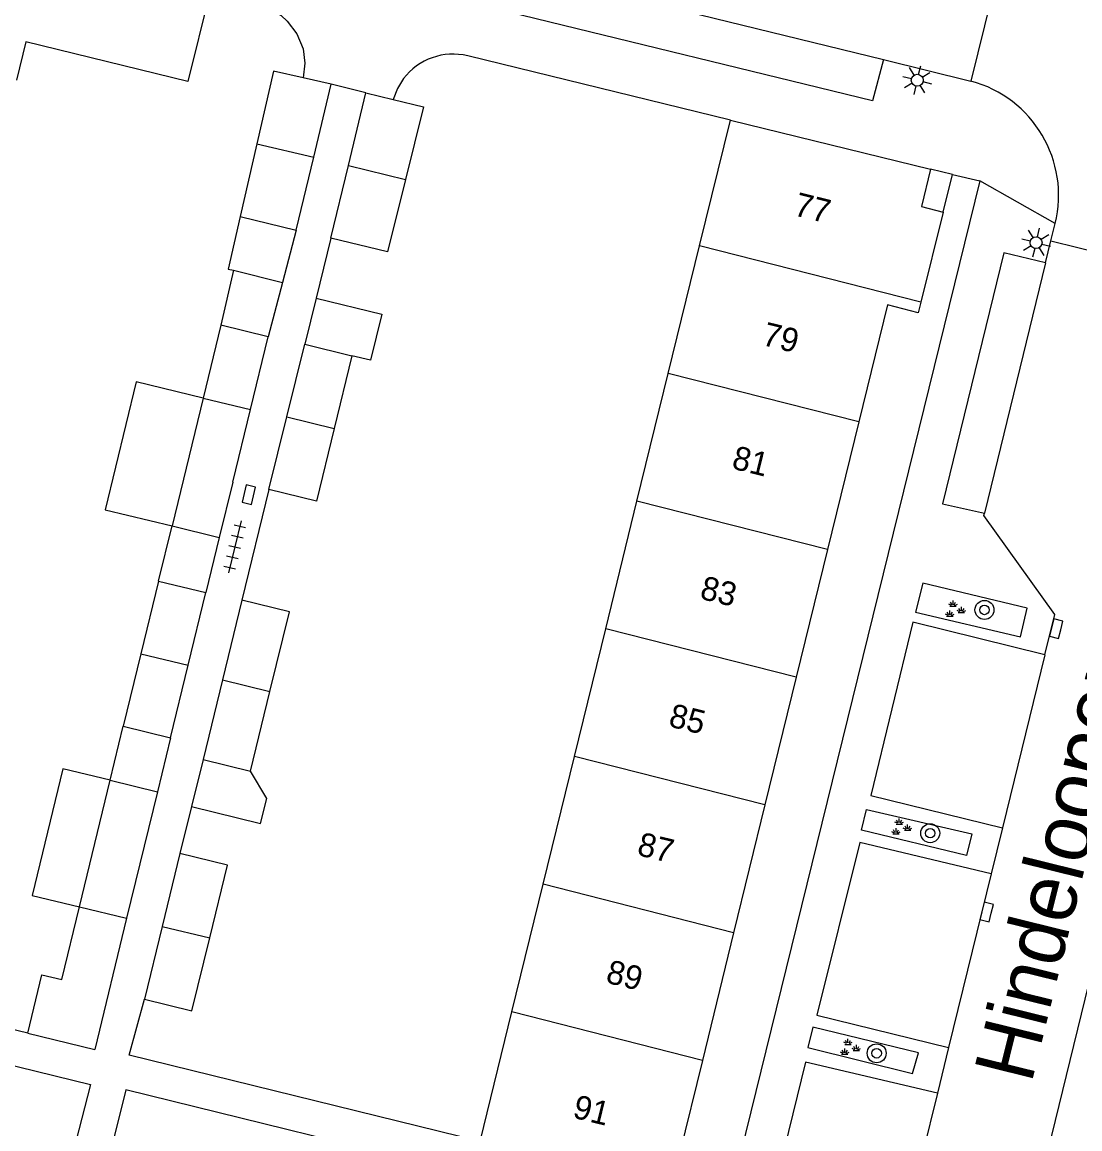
# Model space of a CAD drawing. Extents: x 128000 to 131008, y 398996 to 402500.
# Drawn here: x 128064.32 to 128108.9, y 399441.34 to 399488.01 of the extents above; entities that cross this region are included whole.
import ezdxf

# ---------------------------------------------------------------- set-up
doc = ezdxf.new("R2010")
doc.units = 0
for name, color, linetype in [('gg-afsc-erfafscheiding', 7, 'Continuous'), ('gg-afsc-muur', 7, 'Continuous'), ('gg-anno-huisnummerreeks BGT', 7, 'Continuous'), ('gg-anno-openbare ruimte label', 7, 'Continuous'), ('gg-bbg-bijgebouw', 7, 'Continuous'), ('gg-bbg-gedigitaliseerde bebouwing', 7, 'Continuous'), ('gg-bbg-gedigitaliseerde bijgebouw', 7, 'Continuous'), ('gg-bbg-hoofdgebouw', 7, 'Continuous'), ('gg-bbg-luifel en loopbrug', 7, 'Continuous'), ('gg-bbg-onder overbouw', 7, 'Continuous'), ('gg-bbg-pand overbouw', 7, 'Continuous'), ('gg-bbg-tussenscheiding', 7, 'Continuous'), ('gg-knt-verharding', 7, 'Continuous'), ('gg-knt-verharding nz', 7, 'Continuous'), ('gt-grn-weggrens', 7, 'Continuous'), ('gt-symb-boom', 7, 'Continuous'), ('gt-symb-groenvak', 7, 'Continuous'), ('gt-symb-kolk', 7, 'Continuous'), ('gt-symb-lichtmast', 7, 'Continuous'), ('gt-symb-tegel verharding', 7, 'Continuous')]:
    doc.layers.add(name, color=color, linetype=linetype)

# ---------------------------------------------------------------- blocks, each defined once
blk = doc.blocks.new('gt0-BOOM')
at = {"layer": 'gt-symb-boom'}
for radius in [0.4, 0.2]:
    blk.add_circle((0, 0), radius, dxfattribs=at)
blk = doc.blocks.new('gt0-LMAST')
at = {"layer": 'gt-symb-lichtmast'}
for p, q in [((-0.005, 0.246), (-0.005, 0.621)), ((-0.182, 0.173), (-0.447, 0.438)), ((0.172, 0.173), (0.437, 0.438)), ((-0.255, -0.004), (-0.63, -0.004)), ((-0.182, -0.181), (-0.447, -0.446)), ((-0.005, -0.254), (-0.005, -0.629)), ((0.437, -0.446), (0.172, -0.181)), ((0.245, -0.004), (0.62, -0.004))]:
    blk.add_line(p, q, dxfattribs=at)
blk.add_circle((-0.005, -0.004), 0.25, dxfattribs=at)
blk = doc.blocks.new('gt0-KOLK')
at = {"layer": 'gt-symb-kolk'}
blk.add_lwpolyline([(0, 0), (0.375, 0), (0.375, 0.4), (-0.375, 0.4), (-0.375, 0), (0, 0)], dxfattribs=at)
blk = doc.blocks.new('gt0-GRVAK')
at = {"layer": 'gt-symb-groenvak'}
for p, q in [((-0.11, 0.189), (-0.228, 0.24)), ((-0.182, 0.153), (0.088, 0.153)), ((-0.091, 0.211), (-0.156, 0.322)), ((-0.047, 0.214), (-0.047, 0.393)), ((-0.004, 0.211), (0.061, 0.322)), ((0.015, 0.189), (0.133, 0.24)), ((0.262, -0.052), (0.197, 0.059)), ((0.305, -0.049), (0.305, 0.13)), ((0.349, -0.052), (0.414, 0.059)), ((-0.245, -0.228), (-0.363, -0.177)), ((-0.318, -0.264), (-0.047, -0.264)), ((-0.226, -0.206), (-0.291, -0.095)), ((-0.183, -0.203), (-0.183, -0.024)), ((-0.139, -0.206), (-0.074, -0.095)), ((-0.12, -0.228), (-0.002, -0.177)), ((0.243, -0.074), (0.125, -0.023)), ((0.17, -0.11), (0.441, -0.11)), ((0.368, -0.074), (0.486, -0.023))]:
    blk.add_line(p, q, dxfattribs=at)
blk = doc.blocks.new('gt0-TEG1')
at = {"layer": 'gt-symb-tegel verharding'}
for p, q in [((-1.125, 0), (1.125, 0)), ((-0.9, -0.25), (-0.9, 0.25)), ((-0.45, -0.25), (-0.45, 0.25)), ((0, -0.25), (0, 0.25)), ((0.45, -0.25), (0.45, 0.25)), ((0.9, -0.25), (0.9, 0.25))]:
    blk.add_line(p, q, dxfattribs=at)

msp = doc.modelspace()

# ---------------------------------------------------------------- linework, layer by layer
at = {"layer": 'gg-afsc-erfafscheiding'}
for p, q in [((128077.332, 399478.897), (128076.707, 399476.366)), ((128074.717, 399468.301), (128073.578, 399463.633)), ((128071.46, 399454.927), (128070.97, 399452.944)), ((128064.553, 399445.371), (128054.591, 399447.82))]:
    msp.add_line(p, q, dxfattribs=at)
for points in [[(128083.621, 399440.81), (128068.828, 399444.446), (128069.473, 399446.807)], [(128054.25, 399446.39), (128067.198, 399443.207), (128066.58, 399440.802)], [(128083.28, 399439.39), (128068.686, 399442.977), (128068.061, 399440.444)]]:
    msp.add_lwpolyline(points, dxfattribs=at)
at = {"layer": 'gg-afsc-muur'}
msp.add_line((128094.17, 399483.88), (128083.098, 399486.583), dxfattribs=at)
for points in [[(128072.212, 399489.204), (128074.629, 399488.621), (128075.231, 399488.281), (128075.492, 399488.054), (128075.902, 399487.514), (128076.16, 399486.88), (128076.237, 399486.276), (128076.168, 399485.657)], [(128080.389, 399485.624), (128080.133, 399485.211), (128079.954, 399484.747)]]:
    msp.add_lwpolyline(points, dxfattribs=at)
msp.add_arc((128082.473, 399484.044), 2.615, 76.1629, 142.8255, dxfattribs=at)
at = {"layer": 'gg-bbg-bijgebouw'}
for p, q in [((128077.347, 399485.386), (128076.168, 399485.657)), ((128076.61, 399482.313), (128077.347, 399485.386)), ((128078.068, 399481.964), (128078.803, 399485.031)), ((128078.803, 399485.031), (128079.954, 399484.747)), ((128074.211, 399482.876), (128073.505, 399479.807)), ((128075.872, 399479.239), (128076.61, 399482.313)), ((128077.332, 399478.897), (128078.068, 399481.964)), ((128073.505, 399479.807), (128075.872, 399479.239))]:
    msp.add_line(p, q, dxfattribs=at)
for points in [[(128076.168, 399485.657), (128074.916, 399485.945), (128074.211, 399482.876)], [(128079.954, 399484.747), (128081.229, 399484.432), (128080.475, 399481.378)], [(128080.475, 399481.378), (128079.72, 399478.324), (128077.332, 399478.897)]]:
    msp.add_lwpolyline(points, dxfattribs=at)
at = {"layer": 'gg-bbg-gedigitaliseerde bebouwing'}
msp.add_lwpolyline([(128072.212, 399489.204), (128071.304, 399485.502), (128064.48, 399487.175), (128064.084, 399485.56)], dxfattribs=at)
at = {"layer": 'gg-bbg-gedigitaliseerde bijgebouw'}
for p, q in [((128072.694, 399475.227), (128071.948, 399472.157)), ((128074.686, 399474.743), (128072.694, 399475.227)), ((128073.94, 399471.673), (128074.686, 399474.743)), ((128075.473, 399471.363), (128076.228, 399474.424)), ((128076.228, 399474.424), (128078.216, 399473.94)), ((128078.216, 399473.94), (128077.468, 399470.876)), ((128071.948, 399472.157), (128070.636, 399466.76)), ((128073.193, 399468.603), (128073.94, 399471.673)), ((128074.717, 399468.301), (128075.473, 399471.363)), ((128073.193, 399468.603), (128072.628, 399466.276)), ((128070.636, 399466.76), (128072.628, 399466.276)), ((128070.07, 399464.433), (128069.327, 399461.373)), ((128070.07, 399464.433), (128072.062, 399463.949)), ((128071.318, 399460.889), (128072.062, 399463.949)), ((128073.578, 399463.633), (128072.764, 399460.271)), ((128069.327, 399461.373), (128068.583, 399458.312)), ((128070.574, 399457.828), (128071.318, 399460.889)), ((128072.764, 399460.271), (128071.949, 399456.909)), ((128073.942, 399456.423), (128074.762, 399459.784)), ((128068.583, 399458.312), (128070.574, 399457.828)), ((128071.949, 399456.909), (128073.942, 399456.423)), ((128066.733, 399450.7), (128068.031, 399456.039)), ((128068.031, 399456.039), (128070.02, 399455.555)), ((128070.02, 399455.555), (128068.723, 399450.216)), ((128070.97, 399452.944), (128070.222, 399449.876)), ((128065.988, 399447.634), (128066.733, 399450.7)), ((128068.723, 399450.216), (128067.38, 399444.684)), ((128070.222, 399449.876), (128069.473, 399446.807)), ((128064.553, 399445.371), (128067.38, 399444.684))]:
    msp.add_line(p, q, dxfattribs=at)
for points in [[(128077.468, 399470.876), (128076.721, 399467.812), (128074.717, 399468.301)], [(128074.762, 399459.784), (128075.582, 399463.144), (128073.578, 399463.633)], [(128072.225, 399449.387), (128072.974, 399452.455), (128070.97, 399452.944)], [(128069.473, 399446.807), (128071.476, 399446.318), (128072.225, 399449.387)], [(128064.553, 399445.371), (128065.152, 399447.837), (128065.988, 399447.634)]]:
    msp.add_lwpolyline(points, dxfattribs=at)
at = {"layer": 'gg-bbg-hoofdgebouw'}
for p, q in [((128092.871, 399478.576), (128094.17, 399483.88)), ((128094.17, 399483.88), (128102.61, 399481.81)), ((128103.14, 399480), (128102.193, 399476.203)), ((128091.552, 399473.192), (128092.871, 399478.576)), ((128090.233, 399467.807), (128091.552, 399473.192)), ((128099.582, 399471.147), (128098.263, 399465.763)), ((128088.915, 399462.423), (128090.233, 399467.807)), ((128098.263, 399465.763), (128096.945, 399460.378)), ((128087.596, 399457.038), (128088.915, 399462.423)), ((128096.945, 399460.378), (128095.626, 399454.994)), ((128086.277, 399451.654), (128087.596, 399457.038)), ((128095.626, 399454.994), (128094.307, 399449.609)), ((128084.958, 399446.269), (128086.277, 399451.654)), ((128094.307, 399449.609), (128092.989, 399444.224)), ((128083.621, 399440.81), (128084.958, 399446.269)), ((128092.989, 399444.224), (128091.696, 399438.947))]:
    msp.add_line(p, q, dxfattribs=at)
msp.add_lwpolyline([(128102.193, 399476.203), (128102.08, 399475.75), (128100.79, 399476.08), (128099.582, 399471.147)], dxfattribs=at)
at = {"layer": 'gg-bbg-luifel en loopbrug'}
for p, q in [((128075.872, 399479.239), (128075.288, 399477.026)), ((128073.227, 399477.544), (128072.694, 399475.227)), ((128073.227, 399477.544), (128075.288, 399477.026)), ((128075.288, 399477.026), (128074.686, 399474.743)), ((128076.707, 399476.366), (128076.228, 399474.424)), ((128070.07, 399464.433), (128070.636, 399466.76)), ((128072.628, 399466.276), (128072.062, 399463.949)), ((128068.031, 399456.039), (128068.583, 399458.312)), ((128070.574, 399457.828), (128070.02, 399455.555)), ((128071.949, 399456.909), (128071.46, 399454.927))]:
    msp.add_line(p, q, dxfattribs=at)
for points in [[(128073.505, 399479.807), (128072.997, 399477.597), (128073.227, 399477.544)], [(128076.707, 399476.366), (128079.476, 399475.686), (128079, 399473.747), (128078.216, 399473.94)], [(128071.948, 399472.157), (128069.127, 399472.843), (128067.814, 399467.447), (128070.636, 399466.76)], [(128068.031, 399456.039), (128066.04, 399456.523), (128064.742, 399451.184), (128066.733, 399450.7)], [(128071.46, 399454.927), (128074.371, 399454.211), (128074.632, 399455.271), (128073.942, 399456.423)]]:
    msp.add_lwpolyline(points, dxfattribs=at)
at = {"layer": 'gg-bbg-onder overbouw'}
msp.add_lwpolyline([(128102.61, 399481.81), (128102.22, 399480.23), (128103.14, 399480)], dxfattribs=at)
at = {"layer": 'gg-bbg-pand overbouw'}
for p, q in [((128103.53, 399481.58), (128102.61, 399481.81)), ((128103.14, 399480), (128103.53, 399481.58))]:
    msp.add_line(p, q, dxfattribs=at)
at = {"layer": 'gg-bbg-tussenscheiding'}
for p, q in [((128074.211, 399482.876), (128076.61, 399482.313)), ((128078.068, 399481.964), (128080.475, 399481.378)), ((128102.193, 399476.203), (128092.871, 399478.576)), ((128099.582, 399471.147), (128091.552, 399473.192)), ((128071.948, 399472.157), (128073.94, 399471.673)), ((128075.473, 399471.363), (128077.468, 399470.876)), ((128098.263, 399465.763), (128090.233, 399467.807)), ((128096.945, 399460.378), (128088.915, 399462.423)), ((128069.327, 399461.373), (128071.318, 399460.889)), ((128072.764, 399460.271), (128074.762, 399459.784)), ((128095.626, 399454.994), (128087.596, 399457.038)), ((128094.307, 399449.609), (128086.277, 399451.654)), ((128066.733, 399450.7), (128068.723, 399450.216)), ((128070.222, 399449.876), (128072.225, 399449.387)), ((128092.989, 399444.224), (128084.958, 399446.269))]:
    msp.add_line(p, q, dxfattribs=at)
at = {"layer": 'gg-knt-verharding'}
for p, q in [((128105.487, 399490.346), (128104.305, 399485.523)), ((128100.623, 399486.427), (128104.305, 399485.523)), ((128103.53, 399481.58), (128104.68, 399481.32)), ((128104.68, 399481.32), (128094.109, 399438.309)), ((128107.683, 399478.785), (128107.861, 399479.511)), ((128107.458, 399477.864), (128107.683, 399478.785)), ((128107.683, 399478.785), (128112.527, 399477.576)), ((128105.637, 399454.037), (128105.159, 399452.086)), ((128103.364, 399444.761), (128102.893, 399442.84))]:
    msp.add_line(p, q, dxfattribs=at)
for points in [[(128100.623, 399486.427), (128100.165, 399484.692), (128084.835, 399488.434), (128085.234, 399490.202)], [(128107.458, 399477.864), (128105.702, 399478.285), (128103.11, 399467.698), (128104.874, 399467.298)], [(128112.527, 399477.576), (128112.38, 399476.96), (128115.21, 399471.75), (128105.823, 399433.351)], [(128107.422, 399461.323), (128107.84, 399463.03), (128104.85, 399467.2), (128104.874, 399467.298)], [(128102.275, 399464.342), (128101.97, 399463.129), (128106.398, 399462.091), (128106.684, 399463.291), (128102.275, 399464.342)], [(128107.422, 399461.323), (128101.865, 399462.699), (128100.092, 399455.395), (128105.637, 399454.037)], [(128104.345, 399453.777), (128104.125, 399452.864), (128099.696, 399453.932), (128099.905, 399454.808), (128104.345, 399453.777)], [(128105.159, 399452.086), (128099.619, 399453.418), (128097.815, 399446.137), (128103.364, 399444.761)], [(128097.64, 399445.619), (128097.438, 399444.768), (128101.852, 399443.665), (128102.092, 399444.541), (128097.64, 399445.619)], [(128102.893, 399442.84), (128097.338, 399444.151), (128095.552, 399436.87), (128101.104, 399435.537)]]:
    msp.add_lwpolyline(points, dxfattribs=at)
msp.add_arc((128103.011, 399480.7), 4.994, 346.2296, 74.9776, dxfattribs=at)
at = {"layer": 'gg-knt-verharding nz'}
for p, q in [((128085.234, 399490.202), (128100.623, 399486.427)), ((128107.458, 399477.864), (128104.874, 399467.298)), ((128107.422, 399461.323), (128105.637, 399454.037)), ((128105.159, 399452.086), (128103.364, 399444.761)), ((128102.893, 399442.84), (128101.104, 399435.537))]:
    msp.add_line(p, q, dxfattribs=at)
at = {"layer": 'gt-grn-weggrens'}
for p, q in [((128078.803, 399485.031), (128077.347, 399485.386)), ((128107.861, 399479.511), (128104.68, 399481.32))]:
    msp.add_line(p, q, dxfattribs=at)

# ---------------------------------------------------------------- block references
at = {"layer": 'gt-symb-boom'}
for p in [(128104.879, 399463.22), (128102.592, 399453.804), (128100.334, 399444.523)]:
    msp.add_blockref('gt0-BOOM', p, dxfattribs=at)
at = {"layer": 'gt-symb-groenvak'}
for p in [(128103.603, 399463.219), (128101.334, 399454.037), (128099.174, 399444.747)]:
    msp.add_blockref('gt0-GRVAK', p, dxfattribs=at)
at = {"layer": 'gt-symb-kolk'}
for p, rotation in [((128074.067, 399468.036), 76.51987378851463), ((128108.095, 399462.384), 76.22785456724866), ((128105.164, 399450.43), 76.22785456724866)]:
    msp.add_blockref('gt0-KOLK', p, dxfattribs=dict(at, rotation=rotation))
at = {"layer": 'gt-symb-lichtmast'}
for p, rotation in [((128102.05, 399485.561), -13.772145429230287), ((128107.052, 399478.713), 76.22785456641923)]:
    msp.add_blockref('gt0-LMAST', p, dxfattribs=dict(at, rotation=rotation))
at = {"layer": 'gt-symb-tegel verharding', "rotation": -103.64723833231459}
msp.add_blockref('gt0-TEG1', (128073.28, 399465.881), dxfattribs=at)

# ---------------------------------------------------------------- texts
at = {"layer": 'gg-anno-huisnummerreeks BGT'}
for s, p in [('77', (128096.8, 399479.87)), ('79', (128095.461, 399474.402)), ('81', (128094.185, 399469.192)), ('83', (128092.841, 399463.704)), ('85', (128091.522, 399458.32)), ('87', (128090.193, 399452.895)), ('89', (128088.876, 399447.514)), ('91', (128087.481, 399441.819))]:
    msp.add_text(s, height=1, rotation=346.2, dxfattribs=at).set_placement(p)
at = {"layer": 'gg-anno-openbare ruimte label'}
msp.add_text('Hindeloopenstraat', height=2.5, rotation=76.1, dxfattribs=at).set_placement((128106.853, 399443.207))

doc.saveas('drawing.dxf')
